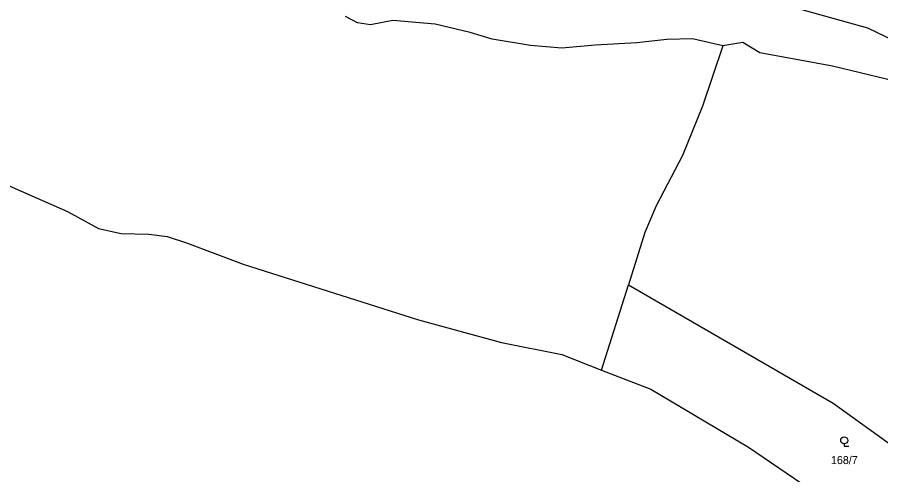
# Model space of a CAD drawing. Extents: x -679220 to -673243, y -1075091 to -1066557.
# Drawn here: x -677024.2 to -676840.9, y -1071084.9 to -1070987.7 of the extents above; entities that cross this region are included whole.
import ezdxf

# ---------------------------------------------------------------- set-up
doc = ezdxf.new("R2010")
doc.units = 0
for name, color, linetype in [('Hranice parcel', 7, 'Continuous'), ('Parcelní čísla', 7, 'Continuous'), ('Značky kultur', 7, 'Continuous')]:
    doc.layers.add(name, color=color, linetype=linetype)

msp = doc.modelspace()

# ---------------------------------------------------------------- linework, layer by layer
at = {"layer": 'Hranice parcel'}
msp.add_line((-676900.14, -1071062.66), (-676894.43, -1071044.54), dxfattribs=at)
for points in [[(-677102.58, -1070978.74), (-677098.26, -1070983.6), (-677089.42, -1070989.76), (-677076.95, -1070997.36), (-677053.83, -1071009.39), (-677025.26, -1071023.81), (-677013.52, -1071028.94), (-677006.94, -1071032.55), (-677002.12, -1071033.66), (-676996.25, -1071033.8), (-676992.35, -1071034.3), (-676988.25, -1071035.62), (-676976.22, -1071040.15), (-676939.02, -1071052), (-676921.36, -1071056.76), (-676908.59, -1071059.36), (-676900.14, -1071062.66)], [(-676835.82, -1070993.8), (-676843.62, -1070990.02), (-676860.89, -1070985.22), (-676862.73, -1070984.96)], [(-676874.39, -1070993.8), (-676880.81, -1070992.29), (-676886.3, -1070992.43), (-676892.65, -1070993.12), (-676901.46, -1070993.64), (-676908.57, -1070994.28), (-676915.24, -1070993.73), (-676923.34, -1070992.4), (-676927.99, -1070990.93), (-676935.44, -1070989.16), (-676944.46, -1070988.39), (-676949.18, -1070989.32), (-676951.91, -1070988.93), (-676954.49, -1070987.56)], [(-676874.39, -1070993.8), (-676878.73, -1071006.62), (-676882.95, -1071017.05), (-676888.56, -1071027.75), (-676890.93, -1071033.45), (-676894.43, -1071044.54)], [(-676793.14, -1071053.68), (-676795.69, -1071046.96), (-676800.86, -1071039.72), (-676803.6, -1071036.35), (-676809.36, -1071029.78), (-676818.33, -1071023.64), (-676822.56, -1071018.06), (-676825.84, -1071016.66), (-676830.38, -1071010.75), (-676835.69, -1071003.1), (-676839.38, -1071000.91), (-676851.08, -1070998.12), (-676866.49, -1070995.3), (-676870.16, -1070993.05), (-676874.39, -1070993.8)], [(-676894.43, -1071044.54), (-676850.95, -1071069.63), (-676837.57, -1071079.26), (-676834.92, -1071075.55)], [(-676900.14, -1071062.66), (-676889.69, -1071066.67), (-676868.93, -1071079.04), (-676857.6, -1071086.69)]]:
    msp.add_lwpolyline(points, dxfattribs=at)
at = {"layer": 'Značky kultur'}
for p, q in [((-676848.61, -1071078.32), (-676848.61, -1071078.82)), ((-676848.61, -1071078.82), (-676847.61, -1071078.82))]:
    msp.add_line(p, q, dxfattribs=at)
msp.add_circle((-676848.61, -1071077.57), 0.75, dxfattribs=at)

# ---------------------------------------------------------------- texts
at = {"layer": 'Parcelní čísla'}
msp.add_text('168/7', height=1.7, dxfattribs=at).set_placement((-676851.43, -1071082.6))

doc.saveas('drawing.dxf')
